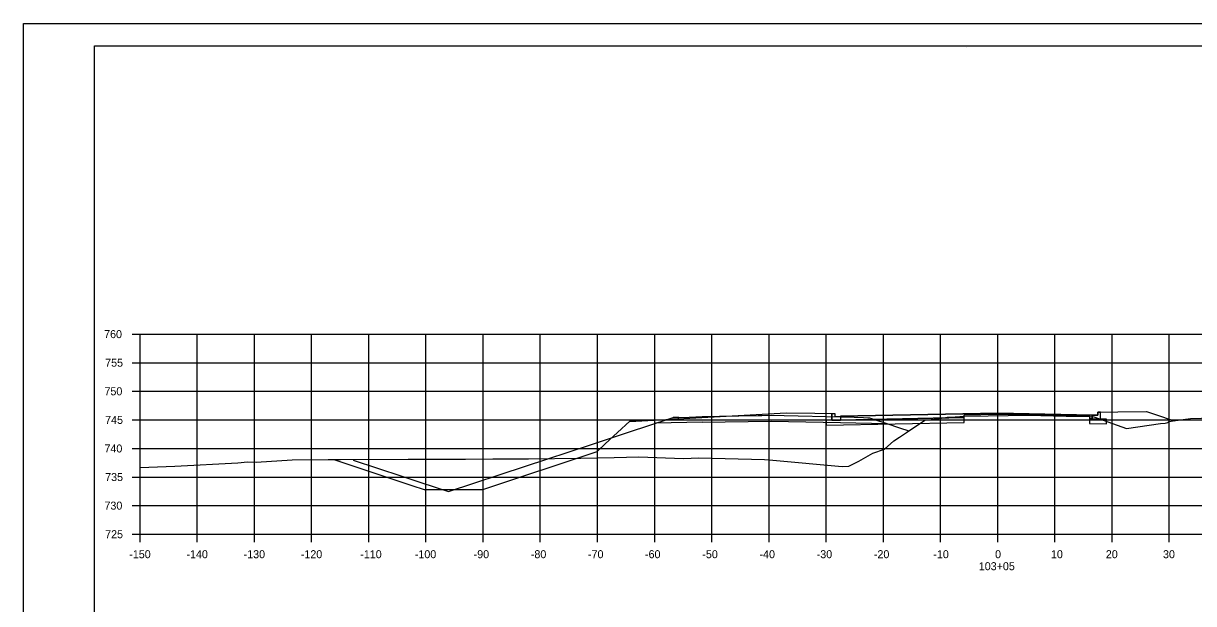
# Model space of a CAD drawing. Extents: x 1202951 to 1376887, y 378065 to 728038.
# Drawn here: x 1374114.6 to 1374319.2, y 378658.4 to 378759.9 of the extents above; entities that cross this region are included whole.
import ezdxf

# ---------------------------------------------------------------- set-up
doc = ezdxf.new("R2010")
doc.units = 0
for name, color, linetype in [('Default', 7, 'Continuous'), ('R_Alt Surface', 7, 'Continuous'), ('R_Axis', 7, 'Continuous'), ('R_Axis Annot', 7, 'Continuous'), ('R_Exist Surface', 7, 'Continuous'), ('R_Fin Surface', 7, 'Continuous'), ('R_Grid', 7, 'Continuous'), ('R_No Plot', 7, 'Continuous'), ('R_Proposed Road', 7, 'Continuous')]:
    doc.layers.add(name, color=color, linetype=linetype)

msp = doc.modelspace()

# ---------------------------------------------------------------- linework, layer by layer
at = {"layer": 'Default'}
for points in [[(1374255.98, 378691.68), (1374256.47, 378691.68), (1374256.48, 378691.18), (1374257.48, 378691.2), (1374257.48, 378690.54), (1374255.98, 378690.51)], [(1374302.98, 378691.9), (1374302.49, 378691.9), (1374302.48, 378691.4), (1374301.48, 378691.42), (1374301.48, 378690.76), (1374302.98, 378690.73)]]:
    msp.add_lwpolyline(points, close=True, dxfattribs=at)
at = {"layer": 'R_Alt Surface'}
for points in [[(1374233.26, 378690.16), (1374245.36, 378690.38), (1374257.48, 378690.13)], [(1374255.98, 378691.68), (1374255.98, 378690.51), (1374257.48, 378690.54), (1374279.13, 378690.97), (1374279.13, 378691.47), (1374284.98, 378691.59), (1374301.01, 378691.27), (1374301.01, 378690.77), (1374301.48, 378690.76), (1374302.98, 378690.73), (1374302.98, 378691.9)], [(1374233.26, 378690.16), (1374225.2, 378690.01)], [(1374257.48, 378690.13), (1374265.56, 378689.96)]]:
    msp.add_lwpolyline(points, dxfattribs=at)
for points in [[(1374257.48, 378690.54), (1374255.98, 378690.51), (1374254.98, 378690.49), (1374254.98, 378689.65), (1374279.13, 378690.14), (1374279.13, 378690.97)], [(1374257.48, 378691.2), (1374257.48, 378690.54), (1374279.13, 378690.97), (1374279.13, 378691.47), (1374284.98, 378691.59), (1374301.01, 378691.27), (1374301.01, 378690.77), (1374301.48, 378690.76), (1374301.48, 378691.42), (1374301.48, 378691.42), (1374284.98, 378691.75), (1374257.48, 378691.2)], [(1374303.98, 378690.71), (1374302.98, 378690.73), (1374301.48, 378690.76), (1374301.01, 378690.77), (1374301.01, 378689.93), (1374303.98, 378689.87)]]:
    msp.add_lwpolyline(points, close=True, dxfattribs=at)
at = {"layer": 'R_Axis'}
for p, q in [((1374133.58, 378705.58), (1374134.98, 378705.58)), ((1374134.98, 378670.58), (1374134.98, 378705.58)), ((1374133.58, 378700.58), (1374134.98, 378700.58)), ((1374133.58, 378695.58), (1374134.98, 378695.58)), ((1374133.58, 378690.58), (1374134.98, 378690.58)), ((1374133.58, 378685.58), (1374134.98, 378685.58)), ((1374133.58, 378680.58), (1374134.98, 378680.58)), ((1374133.58, 378675.58), (1374134.98, 378675.58)), ((1374133.58, 378670.58), (1374134.98, 378670.58)), ((1374134.98, 378670.58), (1374434.98, 378670.58)), ((1374134.98, 378669.18), (1374134.98, 378670.58)), ((1374144.98, 378669.18), (1374144.98, 378670.58)), ((1374154.98, 378669.18), (1374154.98, 378670.58)), ((1374164.98, 378669.18), (1374164.98, 378670.58)), ((1374174.98, 378669.18), (1374174.98, 378670.58)), ((1374184.98, 378669.18), (1374184.98, 378670.58)), ((1374194.98, 378669.18), (1374194.98, 378670.58)), ((1374204.98, 378669.18), (1374204.98, 378670.58)), ((1374214.98, 378669.18), (1374214.98, 378670.58)), ((1374224.98, 378669.18), (1374224.98, 378670.58)), ((1374234.98, 378669.18), (1374234.98, 378670.58)), ((1374244.98, 378669.18), (1374244.98, 378670.58)), ((1374254.98, 378669.18), (1374254.98, 378670.58)), ((1374264.98, 378669.18), (1374264.98, 378670.58)), ((1374274.98, 378669.18), (1374274.98, 378670.58)), ((1374284.98, 378669.18), (1374284.98, 378670.58)), ((1374294.98, 378669.18), (1374294.98, 378670.58)), ((1374304.98, 378669.18), (1374304.98, 378670.58)), ((1374314.98, 378669.18), (1374314.98, 378670.58))]:
    msp.add_line(p, q, dxfattribs=at)
at = {"layer": 'R_Exist Surface'}
msp.add_lwpolyline([(1374134.98, 378682.25), (1374141.05, 378682.51), (1374152.09, 378683.09), (1374153.78, 378683.22), (1374155.3, 378683.2), (1374161.58, 378683.59), (1374167.88, 378683.64), (1374170.06, 378683.65), (1374181.84, 378683.73), (1374191.91, 378683.73), (1374196.66, 378683.74), (1374199.02, 378683.74), (1374202.93, 378683.75), (1374212.06, 378683.88), (1374217.91, 378684.01), (1374222.19, 378684.09), (1374230.05, 378683.83), (1374232.71, 378683.94), (1374244.2, 378683.67), (1374245.64, 378683.51), (1374257.77, 378682.44), (1374258.91, 378682.48), (1374260.7, 378683.38), (1374263.12, 378684.78), (1374265.16, 378685.47), (1374266.83, 378686.89), (1374267.8, 378687.53), (1374269, 378688.39), (1374272.24, 378690.55), (1374274.38, 378690.76), (1374275.48, 378690.96), (1374276.12, 378691.05), (1374276.76, 378691.07), (1374279.13, 378691.21), (1374283.3, 378691.29), (1374290.29, 378691.41), (1374296.97, 378691.25), (1374301.01, 378691.18), (1374301.78, 378691.14), (1374307.53, 378689.07), (1374313.44, 378689.94), (1374314.25, 378690.03), (1374314.71, 378690.14), (1374314.93, 378690.28), (1374315.32, 378690.33), (1374315.64, 378690.41), (1374318.72, 378690.82), (1374328.21, 378691.12)], dxfattribs=at)
at = {"layer": 'R_Fin Surface'}
for points in [[(1374168.89, 378683.64), (1374182.52, 378679.1), (1374184.66, 378678.38), (1374192.37, 378678.38), (1374194.91, 378678.38), (1374214.93, 378685.07), (1374216.35, 378686.39), (1374220.66, 378690.38), (1374221.66, 378690.38), (1374247.98, 378691.84), (1374252.98, 378691.74), (1374255.98, 378691.68), (1374256.47, 378691.68), (1374256.48, 378691.18), (1374257.48, 378691.2), (1374284.98, 378691.75), (1374301.48, 378691.42), (1374302.48, 378691.4), (1374302.49, 378691.9), (1374302.98, 378691.9), (1374305.98, 378691.96), (1374310.98, 378692.06), (1374312.56, 378691.54), (1374315.86, 378690.44)], [(1374172.25, 378683.52), (1374180.76, 378680.73), (1374184.09, 378679.64), (1374188.94, 378678.05), (1374202.36, 378682.48), (1374213.75, 378686.23), (1374219.35, 378688.08), (1374225.2, 378690.01), (1374226.45, 378690.42), (1374228.22, 378691), (1374228.74, 378691), (1374229.23, 378691), (1374230.99, 378691.07), (1374233.26, 378691.16), (1374236.33, 378691.22), (1374243.09, 378691.34), (1374243.73, 378691.35), (1374245.36, 378691.38), (1374247.63, 378691.34), (1374257.48, 378691.13), (1374259.88, 378691.03), (1374261.52, 378690.97), (1374262.24, 378690.96), (1374262.53, 378690.96), (1374263.25, 378690.72), (1374265.56, 378689.96), (1374267.81, 378689.21), (1374269.43, 378688.68)]]:
    msp.add_lwpolyline(points, dxfattribs=at)
at = {"layer": 'R_Grid'}
for p, q in [((1374134.98, 378705.58), (1374434.98, 378705.58)), ((1374134.98, 378670.58), (1374134.98, 378705.58)), ((1374144.98, 378670.58), (1374144.98, 378705.58)), ((1374154.98, 378670.58), (1374154.98, 378705.58)), ((1374164.98, 378670.58), (1374164.98, 378705.58)), ((1374174.98, 378670.58), (1374174.98, 378705.58)), ((1374184.98, 378670.58), (1374184.98, 378705.58)), ((1374194.98, 378670.58), (1374194.98, 378705.58)), ((1374204.98, 378670.58), (1374204.98, 378705.58)), ((1374214.98, 378670.58), (1374214.98, 378705.58)), ((1374224.98, 378670.58), (1374224.98, 378705.58)), ((1374234.98, 378670.58), (1374234.98, 378705.58)), ((1374244.98, 378670.58), (1374244.98, 378705.58)), ((1374254.98, 378670.58), (1374254.98, 378705.58)), ((1374264.98, 378670.58), (1374264.98, 378705.58)), ((1374274.98, 378670.58), (1374274.98, 378705.58)), ((1374284.98, 378670.58), (1374284.98, 378705.58)), ((1374294.98, 378670.58), (1374294.98, 378705.58)), ((1374304.98, 378670.58), (1374304.98, 378705.58)), ((1374314.98, 378670.58), (1374314.98, 378705.58)), ((1374134.98, 378700.58), (1374434.98, 378700.58)), ((1374134.98, 378695.58), (1374434.98, 378695.58)), ((1374134.98, 378690.58), (1374434.98, 378690.58)), ((1374134.98, 378685.58), (1374434.98, 378685.58)), ((1374134.98, 378680.58), (1374434.98, 378680.58)), ((1374134.98, 378675.58), (1374434.98, 378675.58)), ((1374134.98, 378670.58), (1374434.98, 378670.58))]:
    msp.add_line(p, q, dxfattribs=at)
at = {"layer": 'R_No Plot'}
for p, q in [((1374114.58, 378759.94), (1374447.91, 378759.94)), ((1374126.98, 378756.04), (1374443.16, 378756.04)), ((1374126.98, 378550.58), (1374126.98, 378756.04)), ((1374279.5, 378755.78), (1374279.5, 378755.78)), ((1374279.5, 378755.78), (1374279.5, 378755.78))]:
    msp.add_line(p, q, dxfattribs=at)
for points in [[(1374114.57, 378759.94), (1374447.91, 378759.94), (1374447.91, 378546.6), (1374114.57, 378546.6)], [(1374360.9, 378756.04), (1374380.52, 378756.04), (1374380.52, 378746.16), (1374396.63, 378746.16), (1374419.83, 378746.16), (1374419.83, 378721.83), (1374443.16, 378721.83), (1374443.16, 378550.58), (1374126.98, 378550.58), (1374126.98, 378756.04)]]:
    msp.add_lwpolyline(points, close=True, dxfattribs=at)
at = {"layer": 'R_Proposed Road'}
for points in [[(1374229.23, 378691), (1374228.22, 378691)], [(1374261.52, 378690.97), (1374262.53, 378690.96)]]:
    msp.add_lwpolyline(points, dxfattribs=at)

# ---------------------------------------------------------------- texts
at = {"layer": 'R_Axis Annot'}
for s, p in [('760', (1374128.69, 378704.88)), ('755', (1374128.87, 378699.88)), ('750', (1374128.75, 378694.88)), ('745', (1374128.87, 378689.88)), ('740', (1374128.75, 378684.88)), ('735', (1374128.87, 378679.88)), ('730', (1374128.75, 378674.88)), ('725', (1374128.87, 378669.88)), ('-150', (1374133.09, 378666.38)), ('-140', (1374143.09, 378666.38)), ('-130', (1374153.09, 378666.38)), ('-120', (1374163.09, 378666.38)), ('-110', (1374173.49, 378666.38)), ('-100', (1374183.03, 378666.38)), ('-90', (1374193.32, 378666.38)), ('-80', (1374203.32, 378666.38)), ('-70', (1374213.32, 378666.38)), ('-60', (1374223.29, 378666.38)), ('-50', (1374233.32, 378666.38)), ('-40', (1374243.32, 378666.38)), ('-30', (1374253.32, 378666.38)), ('-20', (1374263.32, 378666.38)), ('-10', (1374273.72, 378666.38)), ('0', (1374284.52, 378666.38)), ('10', (1374294.29, 378666.38)), ('20', (1374303.89, 378666.38)), ('30', (1374313.89, 378666.38)), ('103+05', (1374281.67, 378664.28))]:
    msp.add_text(s, height=1.4, dxfattribs=at).set_placement(p)

doc.saveas('drawing.dxf')
